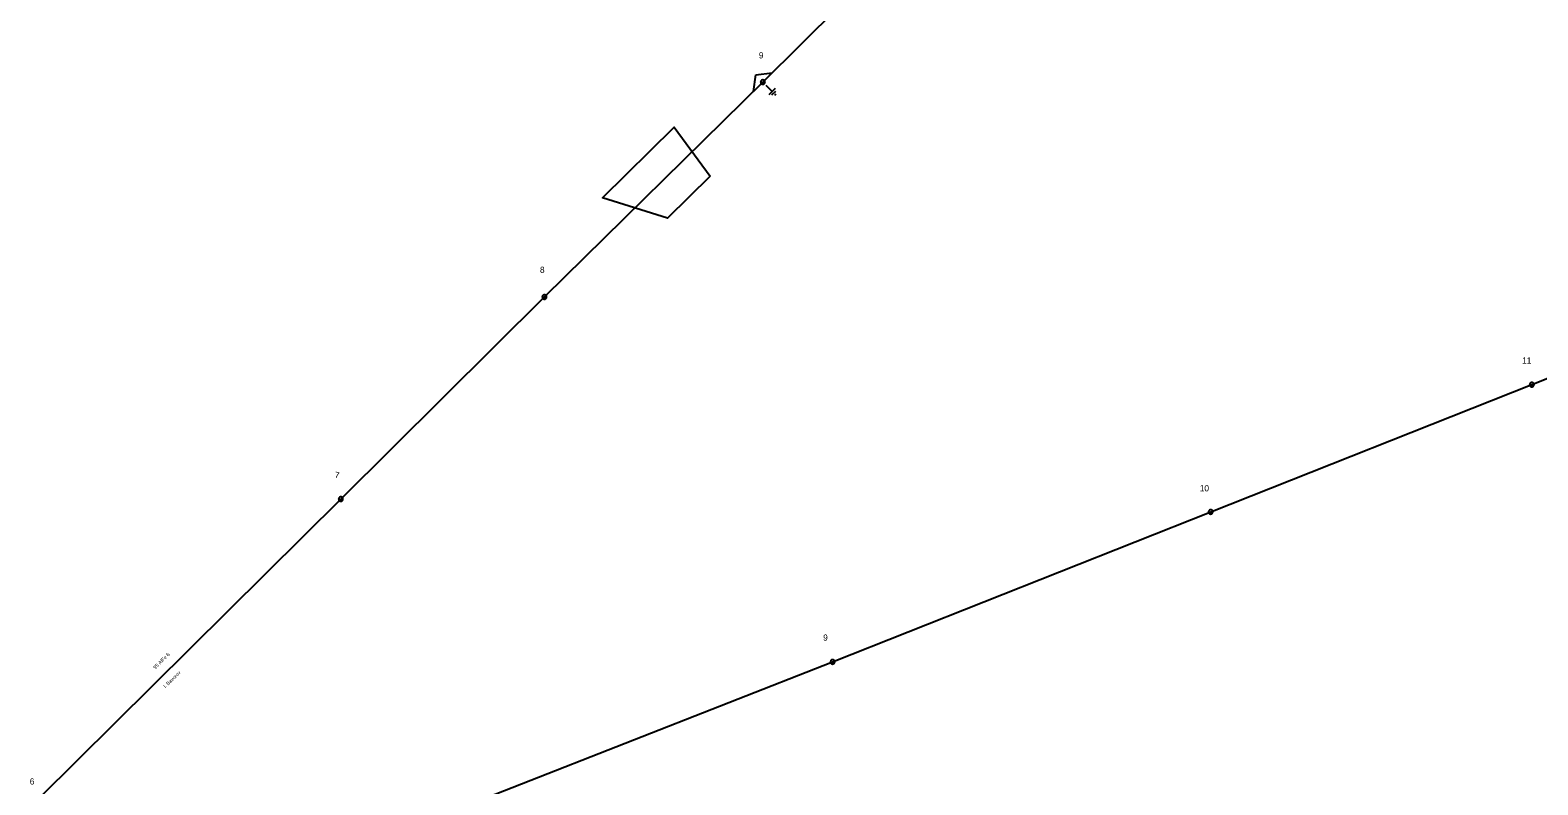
# Model space of a CAD drawing. Extents: x -788491 to -785797, y -1154753 to -1152002.
# Drawn here: x -787118.3 to -786692.2, y -1153491.5 to -1153278 of the extents above; entities that cross this region are included whole.
import ezdxf

# ---------------------------------------------------------------- set-up
doc = ezdxf.new("R2010")
doc.units = 0
for name, color, linetype in [('Vrstva 1', 7, 'Continuous'), ('Vrstva 13', 7, 'Continuous'), ('Vrstva 14', 7, 'Continuous'), ('Vrstva 15', 7, 'Continuous'), ('Vrstva 18', 7, 'Continuous'), ('Vrstva 2', 7, 'Continuous'), ('Vrstva 3', 7, 'Continuous'), ('Vrstva 35', 7, 'Continuous')]:
    doc.layers.add(name, color=color, linetype=linetype)

# ---------------------------------------------------------------- blocks, each defined once
blk = doc.blocks.new('VN860')
at = {"layer": 'Vrstva 15'}
for points in [[(-3.74, 0), (0.01, 2.82)], [(0.01, 2.82), (3.76, 0)]]:
    blk.add_lwpolyline(points, dxfattribs=at)
blk = doc.blocks.new('VN440')
at = {"layer": 'Vrstva 2'}
for points in [[(1.22, 0), (1.21, 0.13), (1.19, 0.25), (1.16, 0.38), (1.11, 0.5), (1.05, 0.61), (0.98, 0.72), (0.9, 0.82), (0.81, 0.91), (0.71, 0.99), (0.6, 1.06), (0.49, 1.12), (0.37, 1.16), (0.25, 1.2), (0.12, 1.22), (-0.01, 1.22), (-0.14, 1.22), (-0.26, 1.2), (-0.39, 1.16), (-0.51, 1.12), (-0.62, 1.06), (-0.73, 0.99), (-0.83, 0.91), (-0.92, 0.82), (-1, 0.72), (-1.07, 0.61), (-1.13, 0.5), (-1.18, 0.38), (-1.21, 0.25), (-1.23, 0.13), (-1.24, 0), (-1.23, -0.13), (-1.21, -0.26), (-1.18, -0.38), (-1.13, -0.5), (-1.07, -0.62), (-1, -0.73), (-0.92, -0.83), (-0.83, -0.92), (-0.73, -1), (-0.62, -1.07), (-0.51, -1.13), (-0.39, -1.17), (-0.26, -1.2), (-0.14, -1.23), (-0.01, -1.23), (0.12, -1.23), (0.25, -1.2), (0.37, -1.17), (0.49, -1.13), (0.6, -1.07), (0.71, -1), (0.81, -0.92), (0.9, -0.83), (0.98, -0.73), (1.05, -0.62), (1.11, -0.5), (1.16, -0.38), (1.19, -0.26), (1.21, -0.13), (1.22, 0)], [(-1.24, 0), (1.22, 0)], [(-1.18, -0.34), (1.1, -0.34)], [(-1.01, -0.63), (0.97, -0.63)], [(-0.74, -0.92), (0.68, -0.92)]]:
    blk.add_lwpolyline(points, dxfattribs=at)
blk = doc.blocks.new('VN810')
at = {"layer": 'Vrstva 14'}
for points in [[(1.25, -3.75), (-1.25, -3.75)], [(0, -1.25), (0, -3.75)], [(0.77, -4.37), (-0.8, -4.37)], [(0, -5), (-0.25, -5)], [(0.27, -5), (0, -5)]]:
    blk.add_lwpolyline(points, dxfattribs=at)

msp = doc.modelspace()

# ---------------------------------------------------------------- linework, layer by layer
at = {"layer": 'Vrstva 1'}
for points in [[(-786846.74, -1153228.64), (-786911.24, -1153292.69), (-786972.96, -1153353.46), (-787030.52, -1153410.63), (-787115.83, -1153495.28)], [(-787008.76, -1153502.68), (-786891.51, -1153456.67), (-786784.65, -1153414.25), (-786693.88, -1153378.27), (-786613.46, -1153346.39), (-786516.04, -1153308.16)]]:
    msp.add_lwpolyline(points, dxfattribs=at)
at = {"layer": 'Vrstva 35'}
msp.add_lwpolyline([(-786926.13, -1153319.28), (-786938.2, -1153331.16), (-786956.57, -1153325.39), (-786936.34, -1153305.48)], close=True, dxfattribs=at)

# ---------------------------------------------------------------- block references
at = {"layer": 'Vrstva 13'}
for p, xscale, yscale, rotation in [((-786911.24, -1153292.69), 0.5000000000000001, 0.4999999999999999, 44.54154167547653), ((-786972.96, -1153353.46), 0.5, 0.5, 44.323649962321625), ((-786693.88, -1153378.27), 0.5, 0.49999999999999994, 21.399183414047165), ((-787030.52, -1153410.63), 0.49999999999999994, 0.5000000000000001, 45.14214162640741), ((-786784.65, -1153414.25), 0.5, 0.49999999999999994, 21.399183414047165), ((-786891.51, -1153456.67), 0.5, 0.49999999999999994, 21.399183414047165)]:
    msp.add_blockref('VN440', p, dxfattribs=dict(at, xscale=xscale, yscale=yscale, rotation=rotation))
at = {"layer": 'Vrstva 15', "rotation": 43.91158606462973}
msp.add_blockref('VN810', (-786911.24, -1153292.69), dxfattribs=at)
at = {"layer": 'Vrstva 18', "rotation": 44.68025553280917}
msp.add_blockref('VN860', (-786911.24, -1153292.69), dxfattribs=at)

# ---------------------------------------------------------------- texts
at = {"layer": 'Vrstva 14'}
for s, p in [('9', (-786912.36, -1153286)), ('8', (-786974.23, -1153346.65)), ('11', (-786696.63, -1153372.31)), ('10', (-786787.74, -1153408.44)), ('9', (-786894.19, -1153450.69)), ('6', (-787118.45, -1153491.37))]:
    msp.add_text(s, height=1.75, dxfattribs=at).set_placement(p)
msp.add_text('7', height=1.75, rotation=350.789, dxfattribs=at).set_placement((-787032.34, -1153404.6))
at = {"layer": 'Vrstva 2'}
msp.add_text('95 AlFe 6', height=1, rotation=44.777, dxfattribs=at).set_placement((-787082.95, -1153458.85))
at = {"layer": 'Vrstva 3'}
msp.add_text('l. Bavorov', height=1, rotation=44.777, dxfattribs=at).set_placement((-787080.05, -1153464.15))

doc.saveas('drawing.dxf')
